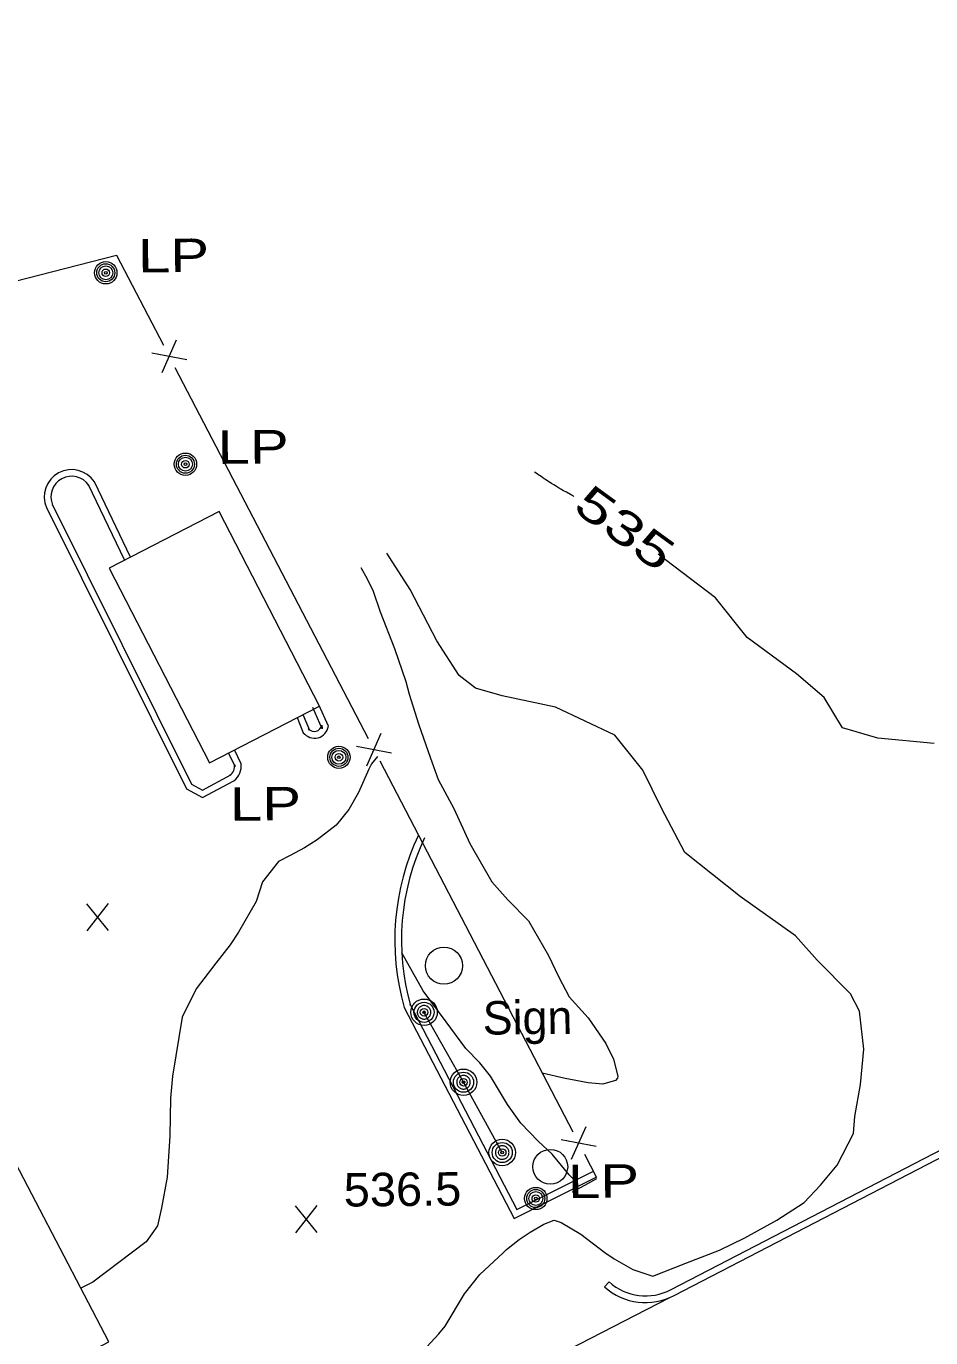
# Model space of a CAD drawing. Extents: x 2361284 to 2366480, y 6976556 to 6985346.
# Drawn here: x 2361833.4 to 2361963.2, y 6977950.5 to 6978138.6 of the extents above; entities that cross this region are included whole.
import ezdxf
from ezdxf.enums import TextEntityAlignment as Align

# ---------------------------------------------------------------- set-up
doc = ezdxf.new("R2010")
doc.units = 0
doc.header["$LTSCALE"] = 1.9
for name, color, linetype, lineweight in [('10', 7, 'Continuous', 13), ('12', 7, 'Continuous', 13), ('13', 7, 'Continuous', 13), ('3', 7, 'Continuous', 13), ('4', 7, 'Continuous', 13), ('5', 7, 'Continuous', 13), ('7', 7, 'Continuous', 13), ('9', 7, 'Continuous', 13)]:
    doc.layers.add(name, color=color, linetype=linetype, lineweight=lineweight)

msp = doc.modelspace()

# ---------------------------------------------------------------- linework, layer by layer
at = {"layer": '10'}
for p, q in [((2361896.152, 6977987.145), (2361890.476, 6977997.211)), ((2361901.707, 6977977.067), (2361896.152, 6977987.145))]:
    msp.add_line(p, q, dxfattribs=at)
for centre, radius in [((2361893.344, 6978003.868), 2.661), ((2361908.597, 6977975.024), 2.496)]:
    msp.add_circle(centre, radius, dxfattribs=at)
at = {"layer": '12'}
for p, q in [((2361845.258, 6978008.895), (2361842.141, 6978012.746)), ((2361842.178, 6978008.866), (2361845.221, 6978012.775)), ((2361875.191, 6977965.586), (2361872.074, 6977969.437)), ((2361872.111, 6977965.557), (2361875.154, 6977969.466))]:
    msp.add_line(p, q, dxfattribs=at)
for points in [[(2361911.984, 6978071.179), (2361911.906, 6978071.229), (2361911.747, 6978071.326), (2361911.587, 6978071.42), (2361911.479, 6978071.48), (2361911.261, 6978071.599), (2361911.152, 6978071.658), (2361910.933, 6978071.773), (2361910.493, 6978072.003), (2361910.275, 6978072.121), (2361910.13, 6978072.201), (2361910.059, 6978072.241), (2361909.951, 6978072.303), (2361909.792, 6978072.399), (2361909.328, 6978072.686), (2361909.098, 6978072.831), (2361908.752, 6978073.049), (2361908.408, 6978073.27), (2361908.237, 6978073.381), (2361907.894, 6978073.605), (2361907.724, 6978073.717), (2361907.469, 6978073.887), (2361907.129, 6978074.115), (2361906.96, 6978074.23), (2361906.707, 6978074.404), (2361906.329, 6978074.667)], [(2361963.663, 6978035.719), (2361955.565, 6978036.492), (2361950.491, 6978037.974), (2361947.889, 6978042.34), (2361943.927, 6978045.712), (2361936.837, 6978050.965), (2361932.273, 6978056.652), (2361925.1, 6978062.064), (2361924.083, 6978062.874)]]:
    msp.add_lwpolyline(points, dxfattribs=at)
at = {"layer": '13'}
for points in [[(2361890.338, 6977948.587), (2361892.615, 6977951.059), (2361893.535, 6977952.138), (2361896.29, 6977956.804), (2361898.483, 6977959.575), (2361901.844, 6977962.667), (2361902.329, 6977963.162), (2361904.126, 6977964.6), (2361905.736, 6977965.645), (2361907.655, 6977966.784), (2361909.161, 6977967.358), (2361910.164, 6977967.017), (2361913, 6977965.334), (2361916.425, 6977962.746), (2361917.784, 6977961.809), (2361920.438, 6977960.304), (2361923.307, 6977959.351), (2361928.039, 6977961.196), (2361932.883, 6977963.062), (2361936.516, 6977964.838), (2361941.072, 6977967.381), (2361945.008, 6977969.908), (2361947.355, 6977972.38), (2361949.727, 6977975.253), (2361952.074, 6977979.816), (2361952.271, 6977982.248), (2361953.108, 6977986.827), (2361953.569, 6977991.881), (2361952.962, 6977997.322), (2361951.654, 6977999.852), (2361946.868, 6978004.637), (2361943.774, 6978008.149), (2361935.85, 6978013.784), (2361927.879, 6978020.108), (2361924.569, 6978026.466), (2361921.867, 6978031.922), (2361917.86, 6978036.924), (2361909.371, 6978040.963), (2361901.704, 6978042.56), (2361897.874, 6978043.674), (2361895.556, 6978045.486), (2361892.34, 6978050.462), (2361888.51, 6978057.806), (2361885.159, 6978063.064)], [(2361881.408, 6978061.008), (2361882.324, 6978059.357), (2361883.221, 6978057.595), (2361884.219, 6978054.615), (2361886.26, 6978049.354), (2361887.905, 6978044.639), (2361888.372, 6978042.794), (2361889.713, 6978038.576), (2361891.41, 6978033.612), (2361892.519, 6978030.573), (2361894.769, 6978026.413), (2361897.085, 6978021.386), (2361900.218, 6978015.875), (2361902.522, 6978013.317), (2361905.461, 6978010.305), (2361908.339, 6978005.341), (2361909.758, 6978002.304), (2361911.296, 6977999.419), (2361914.045, 6977996.396), (2361916.57, 6977992.69), (2361917.671, 6977990.48), (2361918.305, 6977988.016), (2361918.217, 6977987.735), (2361917.931, 6977987.392), (2361916.155, 6977986.875), (2361914.033, 6977987.085), (2361910.747, 6977987.704), (2361907.439, 6977988.473)], [(2361883.816, 6978033.86), (2361882.966, 6978032.822), (2361882.593, 6978032.038), (2361881.085, 6978028.713), (2361879.708, 6978026.28), (2361877.88, 6978024.013), (2361875.18, 6978021.897), (2361873.34, 6978020.77), (2361871.31, 6978019.69), (2361869.638, 6978018.835), (2361867.327, 6978015.912), (2361866.434, 6978013.074), (2361863.885, 6978008.679), (2361862.682, 6978006.857), (2361860.647, 6978004.237), (2361857.802, 6978000.56), (2361855.79, 6977996.491), (2361854.411, 6977988.038), (2361854.121, 6977984.884), (2361854.052, 6977979.454), (2361853.658, 6977973.53), (2361852.85, 6977969.122), (2361852.295, 6977966.537), (2361850.626, 6977964.271), (2361843.021, 6977958.488), (2361841.269, 6977957.631)], [(2361912.136, 6977973.075), (2361911.289, 6977973.877), (2361908.891, 6977976.825), (2361906.872, 6977978.706), (2361904.357, 6977981.272), (2361902.451, 6977983.964), (2361900.013, 6977988.022), (2361898.495, 6977989.928), (2361896.496, 6977991.979), (2361893.67, 6977995.802), (2361890.387, 6978000.28), (2361887.315, 6978005.701)]]:
    msp.add_lwpolyline(points, dxfattribs=at)
at = {"layer": '3'}
for p, q in [((2361917.025, 6977958.511), (2361916.382, 6977957.795)), ((2361876.992, 6977931.239), (2361925.656, 6977956.223))]:
    msp.add_line(p, q, dxfattribs=at)
for points in [[(2361925.92, 6977957.416), (2361925.935, 6977957.426), (2361990.471, 6977990.852), (2362061.364, 6978027.747), (2362139.514, 6978068.253), (2362228.936, 6978114.845), (2362275.302, 6978138.628)], [(2361926.374, 6977956.57), (2361926.373, 6977956.57), (2361990.909, 6977989.996), (2362061.803, 6978026.891), (2362139.952, 6978067.397), (2362229.374, 6978113.989), (2362275.74, 6978137.772)], [(2361847.556, 6978062.067), (2361842.364, 6978072.858), (2361842.43, 6978072.745)], [(2361848.422, 6978062.485), (2361843.23, 6978073.276), (2361843.23, 6978073.276)], [(2361836.334, 6978069.57), (2361836.335, 6978069.57), (2361856.419, 6978029.218), (2361858.741, 6978027.97), (2361863.238, 6978030.404), (2361863.238, 6978030.404)], [(2361837.218, 6978069.944), (2361837.191, 6978069.998), (2361857.143, 6978029.915), (2361858.741, 6978029.06), (2361862.78, 6978031.25), (2361862.665, 6978031.174)], [(2361875.824, 6978038.372), (2361875.898, 6978037.845), (2361874.549, 6978040.912)], [(2361876.774, 6978038.233), (2361876.774, 6978038.233), (2361875.425, 6978041.301)], [(2361872.293, 6978039.451), (2361873.183, 6978037.279), (2361873.183, 6978037.279)], [(2361873.179, 6978039.819), (2361874.07, 6978037.647), (2361873.939, 6978037.871)], [(2361864.265, 6978032.844), (2361864.266, 6978032.844), (2361863.306, 6978034.815)], [(2361863.314, 6978032.716), (2361863.399, 6978032.426), (2361862.44, 6978034.397)], [(2361887.649, 6977997.874), (2361887.65, 6977997.874), (2361903.397, 6977967.593), (2361915.202, 6977973.545)], [(2361888.572, 6977998.137), (2361888.505, 6977998.312), (2361903.815, 6977968.877), (2361914.774, 6977974.401)]]:
    msp.add_lwpolyline(points, dxfattribs=at)
for centre, radius, start, end in [((2361839.954, 6978071.102), 3.931, 33.57589, 202.93489), ((2361839.954, 6978071.102), 2.971, 33.5759, 202.9349), ((2361874.774, 6978038.525), 2.021, 218.0838, 351.68628), ((2361874.774, 6978038.525), 1.061, 218.08379, 351.68627), ((2361861.68, 6978032.496), 2.609, 306.68314, 7.66537), ((2361861.68, 6978032.496), 1.649, 306.68315, 7.66538), ((2361921.549, 6978007.528), 35.248, 154.69331, 195.89513), ((2361921.549, 6978007.528), 34.288, 154.69331, 195.89513), ((2361922.247, 6977964.273), 8.739, 227.84174, 298.17912), ((2361922.247, 6977964.273), 7.779, 227.84174, 298.17912), ((2362483.249, 6976715.46), 1325.03, 110.41057, 115.26257), ((2362483.249, 6976715.46), 1324.07, 110.41057, 115.26257)]:
    msp.add_arc(centre, radius, start, end, dxfattribs=at)
at = {"layer": '4'}
for centre, radius in [((2361844.855, 6978103.264), 1.6), ((2361844.855, 6978103.264), 1.3), ((2361844.855, 6978103.264), 1), ((2361844.855, 6978103.264), 0.539), ((2361844.855, 6978103.264), 0.192), ((2361856.276, 6978075.801), 1.6), ((2361856.276, 6978075.801), 1.3), ((2361856.276, 6978075.801), 1), ((2361856.276, 6978075.801), 0.539), ((2361856.276, 6978075.801), 0.192), ((2361878.287, 6978033.757), 1.6), ((2361878.287, 6978033.757), 1.3), ((2361878.287, 6978033.757), 1), ((2361878.287, 6978033.757), 0.539), ((2361878.287, 6978033.757), 0.192), ((2361890.496, 6977997.181), 1.9), ((2361890.496, 6977997.181), 1.442), ((2361890.496, 6977997.181), 0.539), ((2361890.496, 6977997.181), 0.192), ((2361896.152, 6977987.145), 1.9), ((2361896.152, 6977987.145), 1.442), ((2361896.152, 6977987.145), 0.539), ((2361896.152, 6977987.145), 0.192), ((2361901.707, 6977977.067), 1.9), ((2361901.707, 6977977.067), 1.442), ((2361901.707, 6977977.067), 0.539), ((2361901.707, 6977977.067), 0.192), ((2361906.52, 6977970.472), 1.6), ((2361906.52, 6977970.472), 1.3), ((2361906.52, 6977970.472), 1), ((2361906.52, 6977970.472), 0.539), ((2361906.52, 6977970.472), 0.192)]:
    msp.add_circle(centre, radius, dxfattribs=at)
for centre, start, end in [((2361890.496, 6977997.181), 174.71552, 185.96556), ((2361890.496, 6977997.181), 163.46611, 174.71615), ((2361890.496, 6977997.181), 185.96287, 197.21291), ((2361890.496, 6977997.181), 152.21535, 163.46538), ((2361890.496, 6977997.181), 140.96646, 152.21649), ((2361890.496, 6977997.181), 129.71376, 140.96379), ((2361890.496, 6977997.181), 118.46406, 129.71409), ((2361890.496, 6977997.181), 107.21593, 118.46597), ((2361890.496, 6977997.181), 95.96582, 107.21585), ((2361890.496, 6977997.181), 84.71553, 95.96557), ((2361890.496, 6977997.181), 73.46552, 84.71555), ((2361890.496, 6977997.181), 62.21535, 73.46538), ((2361890.496, 6977997.181), 50.96397, 62.214), ((2361890.496, 6977997.181), 39.71588, 50.96591), ((2361890.496, 6977997.181), 28.46656, 39.7166), ((2361890.496, 6977997.181), 17.21479, 28.46483), ((2361890.496, 6977997.181), 5.96345, 17.21348), ((2361890.496, 6977997.181), 343.46611, 354.71615), ((2361890.496, 6977997.181), 354.71553, 5.96557), ((2361890.496, 6977997.181), 197.21479, 208.46483), ((2361890.496, 6977997.181), 208.46822, 219.71826), ((2361890.496, 6977997.181), 219.71376, 230.96379), ((2361890.496, 6977997.181), 230.96397, 242.214), ((2361890.496, 6977997.181), 242.21812, 253.46815), ((2361890.496, 6977997.181), 253.46258, 264.71261), ((2361890.496, 6977997.181), 264.71553, 275.96557), ((2361890.496, 6977997.181), 275.96582, 287.21585), ((2361890.496, 6977997.181), 287.21593, 298.46597), ((2361890.496, 6977997.181), 298.46406, 309.71409), ((2361890.496, 6977997.181), 309.71589, 320.96592), ((2361890.496, 6977997.181), 320.96646, 332.21649), ((2361890.496, 6977997.181), 332.21419, 343.46422), ((2361896.152, 6977987.145), 140.96646, 152.21649), ((2361896.152, 6977987.145), 129.71376, 140.96379), ((2361896.152, 6977987.145), 118.46406, 129.71409), ((2361896.152, 6977987.145), 107.21593, 118.46597), ((2361896.152, 6977987.145), 95.96582, 107.21585), ((2361896.152, 6977987.145), 84.71553, 95.96557), ((2361896.152, 6977987.145), 73.46552, 84.71555), ((2361896.152, 6977987.145), 62.21535, 73.46538), ((2361896.152, 6977987.145), 50.96397, 62.214), ((2361896.152, 6977987.145), 39.71588, 50.96591), ((2361896.152, 6977987.145), 28.46656, 39.7166), ((2361896.152, 6977987.145), 174.71552, 185.96556), ((2361896.152, 6977987.145), 163.46611, 174.71615), ((2361896.152, 6977987.145), 185.96287, 197.21291), ((2361896.152, 6977987.145), 152.21535, 163.46538), ((2361896.152, 6977987.145), 197.21479, 208.46483), ((2361896.152, 6977987.145), 208.46822, 219.71826), ((2361896.152, 6977987.145), 219.71376, 230.96379), ((2361896.152, 6977987.145), 230.96397, 242.214), ((2361896.152, 6977987.145), 242.21812, 253.46815), ((2361896.152, 6977987.145), 253.46258, 264.71261), ((2361896.152, 6977987.145), 264.71553, 275.96557), ((2361896.152, 6977987.145), 275.96582, 287.21585), ((2361896.152, 6977987.145), 287.21593, 298.46597), ((2361896.152, 6977987.145), 298.46406, 309.71409), ((2361896.152, 6977987.145), 309.71589, 320.96592), ((2361896.152, 6977987.145), 320.96646, 332.21649), ((2361896.152, 6977987.145), 17.21479, 28.46483), ((2361896.152, 6977987.145), 332.21419, 343.46422), ((2361896.152, 6977987.145), 5.96345, 17.21348), ((2361896.152, 6977987.145), 343.46611, 354.71615), ((2361896.152, 6977987.145), 354.71553, 5.96557), ((2361901.707, 6977977.067), 174.71552, 185.96556), ((2361901.707, 6977977.067), 163.46611, 174.71615), ((2361901.707, 6977977.067), 185.96287, 197.21291), ((2361901.707, 6977977.067), 152.21535, 163.46538), ((2361901.707, 6977977.067), 197.21479, 208.46483), ((2361901.707, 6977977.067), 140.96646, 152.21649), ((2361901.707, 6977977.067), 208.46822, 219.71826), ((2361901.707, 6977977.067), 129.71376, 140.96379), ((2361901.707, 6977977.067), 219.71376, 230.96379), ((2361901.707, 6977977.067), 118.46406, 129.71409), ((2361901.707, 6977977.067), 107.21593, 118.46597), ((2361901.707, 6977977.067), 95.96582, 107.21585), ((2361901.707, 6977977.067), 84.71553, 95.96557), ((2361901.707, 6977977.067), 73.46552, 84.71555), ((2361901.707, 6977977.067), 62.21535, 73.46538), ((2361901.707, 6977977.067), 50.96397, 62.214), ((2361901.707, 6977977.067), 39.71588, 50.96591), ((2361901.707, 6977977.067), 309.71589, 320.96592), ((2361901.707, 6977977.067), 28.46656, 39.7166), ((2361901.707, 6977977.067), 320.96646, 332.21649), ((2361901.707, 6977977.067), 17.21479, 28.46483), ((2361901.707, 6977977.067), 332.21419, 343.46422), ((2361901.707, 6977977.067), 5.96345, 17.21348), ((2361901.707, 6977977.067), 343.46611, 354.71615), ((2361901.707, 6977977.067), 354.71553, 5.96557), ((2361901.707, 6977977.067), 230.96397, 242.214), ((2361901.707, 6977977.067), 242.21812, 253.46815), ((2361901.707, 6977977.067), 253.46258, 264.71261), ((2361901.707, 6977977.067), 264.71553, 275.96557), ((2361901.707, 6977977.067), 275.96582, 287.21585), ((2361901.707, 6977977.067), 287.21593, 298.46597), ((2361901.707, 6977977.067), 298.46406, 309.71409)]:
    msp.add_arc(centre, 0.973, start, end, dxfattribs=at)
at = {"layer": '5'}
msp.add_lwpolyline([(2361915.233, 6977973.296), (2361913.487, 6977972.342), (2361911.732, 6977971.383)], dxfattribs=at)
at = {"layer": '7'}
for points in [[(2361875.517, 6978041.111), (2361861.101, 6978069.026), (2361845.328, 6978060.885), (2361859.734, 6978032.971)], [(2361845.313, 6977949.889), (2361810.355, 6978016.851), (2361781.795, 6978001.938), (2361816.762, 6977934.977)]]:
    msp.add_lwpolyline(points, close=True, dxfattribs=at)
at = {"layer": '9'}
for p, q in [((2361852.931, 6978088.959), (2361854.997, 6978093.639)), ((2361851.454, 6978091.795), (2361856.474, 6978090.803)), ((2361854.774, 6978089.676), (2361882.472, 6978036.447)), ((2361882.289, 6978032.535), (2361884.354, 6978037.225)), ((2361880.812, 6978035.371), (2361885.831, 6978034.379)), ((2361884.132, 6978033.253), (2361911.83, 6977980.033)), ((2361911.647, 6977976.121), (2361913.723, 6977980.801)), ((2361910.17, 6977978.957), (2361915.2, 6977977.965)), ((2361913.491, 6977976.839), (2361915.233, 6977973.495))]:
    msp.add_line(p, q, dxfattribs=at)
msp.add_lwpolyline([(2361802.386, 6978094.518), (2361846.38, 6978105.808), (2361853.114, 6978092.871)], dxfattribs=at)

# ---------------------------------------------------------------- texts
at = {"layer": '12', "width": 1.45}
msp.add_text(' 535 ', height=4.8, rotation=323.954, dxfattribs=at).set_placement((2361917.913, 6978064.714), align=Align.CENTER)
at = {"layer": '12', "width": 1.05}
msp.add_text('536.5', height=4.799, rotation=0.545, dxfattribs=at).set_placement((2361879, 6977969.31))
at = {"layer": '4', "width": 1.3}
for p in [(2361844.855, 6978103.264), (2361856.276, 6978075.801), (2361858.043, 6978024.604), (2361906.52, 6977970.472)]:
    msp.add_text('  LP', height=4.799, rotation=0.545, dxfattribs=at).set_placement(p)
at = {"layer": '4'}
msp.add_text('Sign', height=4.799, rotation=0.545, dxfattribs=at).set_placement((2361898.936, 6977993.972))

doc.saveas('drawing.dxf')
